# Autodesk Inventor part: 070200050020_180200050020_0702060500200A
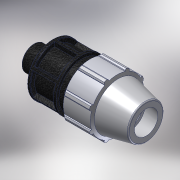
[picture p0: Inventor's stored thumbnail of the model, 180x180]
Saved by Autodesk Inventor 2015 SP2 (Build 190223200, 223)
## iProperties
Created: 2017-02
Part Number: 070200050020_180200050020_0702060500200A
Material: PVC-Piping
Description: PLASSON MALE ADAPTOR 50-2"
Document SubType Name: Modeling
Designer: KIM
Mass: 92.6774 g
Surface Area: 199.44 cm^2
Volume: 66.1981 cm^3
Density: 1.4 g/cm^3
Appearance: PTFE
Author: KIM
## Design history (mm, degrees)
derived "07020.ipt"
feature "Solid1::07020.ipt"
tag "TaggingFeature1"
body "Solid1"
other parameters: "d5" = 35, "d7" = 96, "d8" = 72, "d11" = 4, "d12" = 76.8, "d13" = 120 deg, "d14" = 75, "d15" = 8 deg, "d16" = 86.4, "d18" = 2.5, "d19" = 35 deg, "d20" = 17.5 deg, "d21" = 89.28, "d23" = 0, "d25" = 360 deg, "d27" = 1.92, "d34" = 4.8, "d36" = 0, "d42" = 35, "d43" = 2.88, "d46" = 1.5, "d49" = 109, "d52" = 26, "d53" = 1, "d55" = 360 deg, "d57" = 59.614, "d58" = 41.7298, "d59" = 28, "E_" = 96, "l_" = 109, "l_2" = 26, "R_" = 59.614
